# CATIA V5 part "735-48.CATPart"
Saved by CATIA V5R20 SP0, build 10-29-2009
Part number: 735-48
Bounding box of the stored display mesh (mm): x -40 to 40, y -40 to 40, z -47 to 50
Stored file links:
  C:\Users\Utente\Desktop\IO LAVORO\3D X SITO CF\X SITO\735\735-48.CATPart
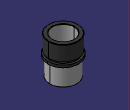
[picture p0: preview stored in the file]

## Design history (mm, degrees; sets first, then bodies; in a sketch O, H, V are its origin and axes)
Set1
  DatumSurface1 to DatumSurface25 "735-48"
Body1 (main body)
